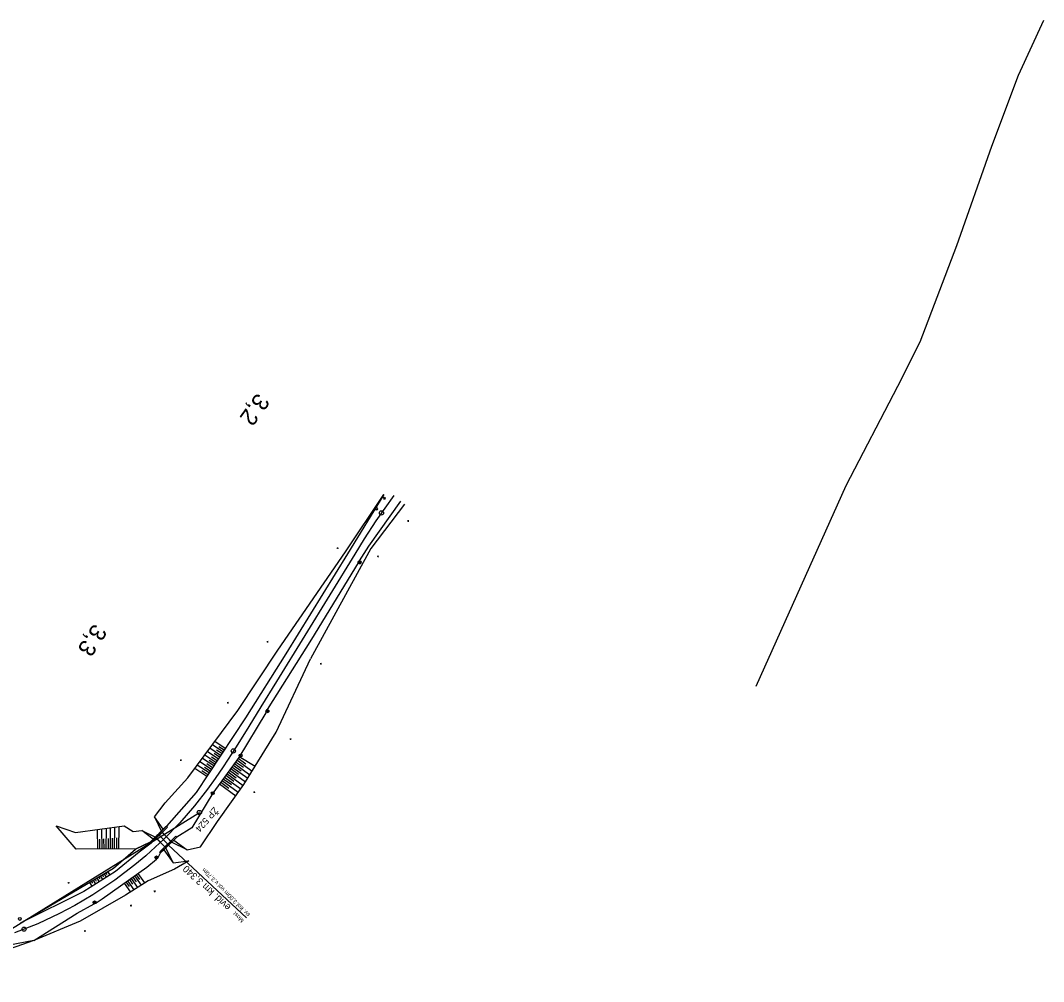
# Model space of a CAD drawing. Extents: x -738085 to -734426, y -1122197 to -1119748.
# Drawn here: x -736607.8 to -736243, y -1121765.3 to -1121422.7 of the extents above; entities that cross this region are included whole.
import ezdxf

# ---------------------------------------------------------------- set-up
doc = ezdxf.new("R2010")
doc.units = 0
for name, color, linetype in [('Polygon ku', 7, 'Continuous'), ('Vrstva 1', 7, 'Continuous'), ('Vrstva 11', 7, 'Continuous'), ('Vrstva 12', 7, 'Continuous'), ('Vrstva 17', 7, 'Continuous'), ('Vrstva 18', 7, 'Continuous'), ('Vrstva 4', 7, 'Continuous'), ('Vrstva 48', 7, 'Continuous'), ('Vrstva 49', 7, 'Continuous'), ('Vrstva 63', 7, 'Continuous'), ('Vrstva 7', 7, 'Continuous')]:
    doc.layers.add(name, color=color, linetype=linetype)

msp = doc.modelspace()

# ---------------------------------------------------------------- linework, layer by layer
at = {"layer": 'Polygon ku'}
for points in [[(-736242.99, -1121422.7), (-736252.08, -1121442.26), (-736261.55, -1121467.67), (-736274.03, -1121502.97), (-736287.1, -1121537.41), (-736295.04, -1121553.12)], [(-736295.04, -1121553.12), (-736313.43, -1121588.53), (-736345.56, -1121660.08)]]:
    msp.add_lwpolyline(points, dxfattribs=at)
at = {"layer": 'Vrstva 1'}
msp.add_lwpolyline([(-736474.59, -1121592.04), (-736481.1, -1121601.1), (-736485.16, -1121607.48), (-736488.53, -1121612.91), (-736506.33, -1121641.86), (-736516.48, -1121658.33), (-736522.03, -1121667.33), (-736526.39, -1121674.4), (-736530.86, -1121681.54), (-736535.51, -1121688.71), (-736538.31, -1121692.85), (-736541.08, -1121696.68), (-736545.71, -1121702.61), (-736550.96, -1121708.65), (-736556.62, -1121714.46), (-736561.26, -1121718.81), (-736563.11, -1121720.47), (-736566.92, -1121723.66), (-736574.05, -1121729.09), (-736581.91, -1121734.35), (-736588.31, -1121738.11), (-736593.86, -1121741.02), (-736601.6, -1121744.63), (-736609.85, -1121747.92)], dxfattribs=at)
msp.add_lwpolyline([(-736474.59, -1121592.04), (-736481.1, -1121601.1), (-736485.16, -1121607.48), (-736488.53, -1121612.91), (-736506.33, -1121641.86), (-736516.48, -1121658.33), (-736522.03, -1121667.33), (-736526.39, -1121674.4), (-736530.86, -1121681.54), (-736535.51, -1121688.71), (-736538.31, -1121692.85), (-736541.08, -1121696.68), (-736545.71, -1121702.61), (-736550.96, -1121708.65), (-736556.62, -1121714.46), (-736561.26, -1121718.81), (-736563.11, -1121720.47), (-736566.92, -1121723.66), (-736574.05, -1121729.09), (-736581.91, -1121734.35), (-736588.31, -1121738.11), (-736593.86, -1121741.02), (-736601.6, -1121744.63), (-736609.85, -1121747.92)], dxfattribs=at)
at = {"layer": 'Vrstva 11'}
for p, q in [((-736487.1, -1121615.42), (-736486.89, -1121616.32)), ((-736486.73, -1121615.34), (-736486.52, -1121616.23)), ((-736519.97, -1121668.45), (-736519.75, -1121669.35)), ((-736519.6, -1121668.37), (-736519.39, -1121669.25)), ((-736539.47, -1121697.71), (-736539.32, -1121698.62)), ((-736539.1, -1121697.65), (-736538.95, -1121698.56)), ((-736559.44, -1121720.55), (-736559.47, -1121721.47)), ((-736559.07, -1121720.56), (-736559.1, -1121721.48)), ((-736581.37, -1121736.54), (-736581.61, -1121737.44)), ((-736581.01, -1121736.64), (-736581.24, -1121737.52))]:
    msp.add_line(p, q, dxfattribs=at)
for centre in [(-736486.82, -1121615.83), (-736519.69, -1121668.85), (-736539.22, -1121698.14), (-736559.28, -1121721.01), (-736581.32, -1121737.03)]:
    msp.add_circle(centre, 0.5, dxfattribs=at)
at = {"layer": 'Vrstva 12'}
for p, q in [((-736486.31, -1121615.66), (-736486.69, -1121616.38)), ((-736519.14, -1121668.73), (-736519.56, -1121669.41)), ((-736558.71, -1121721.04), (-736559.31, -1121721.58)), ((-736580.75, -1121737.18), (-736581.46, -1121737.6))]:
    msp.add_line(p, q, dxfattribs=at)
for points in [[(-736487.37, -1121615.96), (-736486.95, -1121615.28), (-736486.31, -1121615.66), (-736486.69, -1121616.38), (-736487.37, -1121615.96)], [(-736486.95, -1121615.28), (-736486.31, -1121615.66), (-736486.31, -1121615.66)], [(-736487.37, -1121615.96), (-736486.69, -1121616.38), (-736486.69, -1121616.38)], [(-736520.24, -1121668.99), (-736519.82, -1121668.3), (-736519.14, -1121668.73), (-736519.56, -1121669.41), (-736520.24, -1121668.99)], [(-736520.24, -1121668.99), (-736519.56, -1121669.41), (-736519.56, -1121669.41)], [(-736519.82, -1121668.3), (-736519.14, -1121668.73), (-736519.14, -1121668.73)], [(-736559.84, -1121720.98), (-736559.25, -1121720.45), (-736558.71, -1121721.04), (-736559.31, -1121721.58), (-736559.84, -1121720.98)], [(-736559.84, -1121720.98), (-736559.31, -1121721.58), (-736559.31, -1121721.58)], [(-736559.25, -1121720.45), (-736558.71, -1121721.04), (-736558.71, -1121721.04)], [(-736581.88, -1121736.89), (-736581.17, -1121736.46), (-736580.75, -1121737.18), (-736581.46, -1121737.6), (-736581.88, -1121736.89)], [(-736581.88, -1121736.89), (-736581.46, -1121737.6), (-736581.46, -1121737.6)], [(-736581.17, -1121736.46), (-736580.75, -1121737.18), (-736580.75, -1121737.18)]]:
    msp.add_lwpolyline(points, dxfattribs=at)
at = {"layer": 'Vrstva 17'}
for p, q in [((-736555.89, -1121710.05), (-736561.02, -1121715.26)), ((-736557.56, -1121719.19), (-736552.26, -1121714.01))]:
    msp.add_line(p, q, dxfattribs=at)
at = {"layer": 'Vrstva 18'}
for p, q in [((-736561.46, -1121715.57), (-736555.68, -1121709.93)), ((-736555.68, -1121709.93), (-736555.68, -1121709.93)), ((-736559.61, -1121713.85), (-736559.61, -1121713.9)), ((-736559.61, -1121713.85), (-736555.92, -1121717.57)), ((-736559.61, -1121713.9), (-736556.03, -1121717.53)), ((-736558.51, -1121712.82), (-736554.94, -1121716.5)), ((-736557.47, -1121711.79), (-736556.94, -1121712.33)), ((-736557.47, -1121711.79), (-736553.86, -1121715.52)), ((-736556.94, -1121712.33), (-736553.86, -1121715.45)), ((-736552.06, -1121713.78), (-736552.38, -1121713.44)), ((-736552.06, -1121713.78), (-736552.06, -1121713.78)), ((-736555.92, -1121717.57), (-736556.03, -1121717.53)), ((-736554.98, -1121716.66), (-736527.18, -1121742.52)), ((-736553.86, -1121715.52), (-736553.86, -1121715.45)), ((-736558.11, -1121719.07), (-736558.11, -1121719.07)), ((-736558.11, -1121719.07), (-736557.78, -1121719.42)), ((-736557.78, -1121719.42), (-736557.78, -1121719.42))]:
    msp.add_line(p, q, dxfattribs=at)
for points in [[(-736555.68, -1121709.93), (-736556.82, -1121710.98), (-736559.91, -1121706.53), (-736557.47, -1121711.79), (-736556.82, -1121710.98)], [(-736561.46, -1121715.57), (-736561.14, -1121715.9), (-736555.38, -1121710.29), (-736555.68, -1121709.93), (-736561.46, -1121715.57)], [(-736555.38, -1121710.29), (-736561.14, -1121715.9), (-736561.46, -1121715.57), (-736561.46, -1121715.57)], [(-736555.38, -1121710.29), (-736555.38, -1121710.29), (-736555.68, -1121709.93)], [(-736561.46, -1121715.57), (-736560.43, -1121714.5), (-736564.53, -1121711.39), (-736559.61, -1121713.85), (-736560.43, -1121714.5)], [(-736552.38, -1121713.44), (-736552.38, -1121713.44), (-736558.11, -1121719.07)], [(-736552.38, -1121713.44), (-736552.06, -1121713.78), (-736557.78, -1121719.42), (-736558.11, -1121719.07), (-736552.38, -1121713.44)], [(-736552.38, -1121713.44), (-736552.06, -1121713.78), (-736557.78, -1121719.42), (-736558.11, -1121719.07), (-736552.38, -1121713.44)], [(-736552.06, -1121713.78), (-736553.05, -1121714.83), (-736548.27, -1121718.36), (-736553.86, -1121715.52)], [(-736557.78, -1121719.42), (-736556.6, -1121718.34), (-736553.28, -1121722.94), (-736555.92, -1121717.57), (-736556.6, -1121718.34)]]:
    msp.add_lwpolyline(points, dxfattribs=at)
for centre, major_axis, ratio, start_param, end_param in [((-736558.28, -1121713.11), (1.34, 0.78), 0.230715, 6.243976, 9.45735), ((-736554.95, -1121716.49), (-1.09, -1.04), 0.009083, 0.017637, 3.105351)]:
    msp.add_ellipse(centre, major_axis=major_axis, ratio=ratio, start_param=start_param, end_param=end_param, dxfattribs=at)
at = {"layer": 'Vrstva 4'}
msp.add_line((-736555.38, -1121710.29), (-736561.14, -1121715.9), dxfattribs=at)
at = {"layer": 'Vrstva 48'}
for p, q in [((-736535.56, -1121683.4), (-736539.31, -1121680.93)), ((-736534.74, -1121682.14), (-736538.42, -1121679.72)), ((-736538.04, -1121687.16), (-736542, -1121684.54)), ((-736537.21, -1121685.9), (-736541.11, -1121683.34)), ((-736536.39, -1121684.65), (-736540.21, -1121682.13)), ((-736536.8, -1121685.28), (-736538.73, -1121684.01)), ((-736535.97, -1121684.02), (-736537.87, -1121682.78)), ((-736535.15, -1121682.77), (-736537.01, -1121681.55)), ((-736529.73, -1121685.06), (-736524.06, -1121688.5)), ((-736540.51, -1121690.91), (-736544.7, -1121688.16)), ((-736539.69, -1121689.66), (-736543.8, -1121686.95)), ((-736538.86, -1121688.41), (-736542.9, -1121685.75)), ((-736539.27, -1121689.03), (-736541.31, -1121687.69)), ((-736538.45, -1121687.78), (-736540.45, -1121686.46)), ((-736537.62, -1121686.53), (-736539.59, -1121685.23)), ((-736532.35, -1121688.71), (-736526.73, -1121692.81)), ((-736531.91, -1121688.11), (-736529.12, -1121690.14)), ((-736531.47, -1121687.5), (-736525.94, -1121691.53)), ((-736531.03, -1121686.9), (-736528.28, -1121688.9)), ((-736530.58, -1121686.29), (-736525.15, -1121690.26)), ((-736530.14, -1121685.68), (-736527.45, -1121687.65)), ((-736541.34, -1121692.17), (-736545.59, -1121689.36)), ((-736540.92, -1121691.54), (-736543.03, -1121690.15)), ((-736540.1, -1121690.29), (-736542.17, -1121688.92)), ((-736535, -1121692.35), (-736529.2, -1121696.58)), ((-736534.56, -1121691.74), (-736531.67, -1121693.85)), ((-736534.12, -1121691.14), (-736528.33, -1121695.35)), ((-736533.68, -1121690.53), (-736530.8, -1121692.63)), ((-736533.24, -1121689.93), (-736527.52, -1121694.09)), ((-736532.79, -1121689.32), (-736529.96, -1121691.39)), ((-736536.77, -1121694.78), (-736530.95, -1121699.02)), ((-736536.33, -1121694.17), (-736533.42, -1121696.29)), ((-736535.89, -1121693.56), (-736530.08, -1121697.8)), ((-736535.45, -1121692.96), (-736532.54, -1121695.07)), ((-736577.17, -1121717.96), (-736577.11, -1121710.6)), ((-736575.67, -1121717.97), (-736575.61, -1121710.4)), ((-736574.17, -1121717.98), (-736574.11, -1121710.19)), ((-736572.67, -1121717.99), (-736572.61, -1121709.98)), ((-736580.17, -1121717.99), (-736580.28, -1121711.04)), ((-736578.67, -1121717.96), (-736578.78, -1121710.83)), ((-736576.42, -1121717.96), (-736576.39, -1121714.23)), ((-736574.92, -1121717.97), (-736574.89, -1121714.13)), ((-736573.42, -1121717.99), (-736573.39, -1121714.03)), ((-736579.42, -1121717.98), (-736579.47, -1121714.46)), ((-736577.92, -1121717.95), (-736577.98, -1121714.34)), ((-736581.16, -1121728.78), (-736580.76, -1121729.44)), ((-736580.51, -1121728.4), (-736579.74, -1121729.7)), ((-736579.86, -1121728.02), (-736579.48, -1121728.66)), ((-736579.22, -1121727.64), (-736578.47, -1121728.9)), ((-736578.57, -1121727.26), (-736578.2, -1121727.88)), ((-736577.93, -1121726.87), (-736577.2, -1121728.1)), ((-736577.28, -1121726.49), (-736576.93, -1121727.09)), ((-736576.64, -1121726.11), (-736575.94, -1121727.29)), ((-736568.31, -1121728.48), (-736566.02, -1121731.73)), ((-736567.7, -1121728.05), (-736566.54, -1121729.69)), ((-736567.08, -1121727.62), (-736564.76, -1121730.92)), ((-736566.47, -1121727.18), (-736565.3, -1121728.85)), ((-736565.86, -1121726.75), (-736563.49, -1121730.11)), ((-736583.09, -1121729.93), (-736582.28, -1121731.31)), ((-736582.45, -1121729.55), (-736582.04, -1121730.23)), ((-736581.8, -1121729.17), (-736581.01, -1121730.51)), ((-736570.76, -1121730.21), (-736568.56, -1121733.34)), ((-736570.15, -1121729.77), (-736569.04, -1121731.36)), ((-736569.54, -1121729.34), (-736567.29, -1121732.53)), ((-736568.92, -1121728.91), (-736567.79, -1121730.52))]:
    msp.add_line(p, q, dxfattribs=at)
at = {"layer": 'Vrstva 49'}
for p, q in [((-736469.3, -1121601.06), (-736469.8, -1121601.15)), ((-736469.59, -1121600.86), (-736469.51, -1121601.35)), ((-736494.44, -1121610.75), (-736494.93, -1121610.87)), ((-736494.74, -1121610.57), (-736494.62, -1121611.05)), ((-736480.06, -1121613.66), (-736480.54, -1121613.77)), ((-736480.36, -1121613.47), (-736480.24, -1121613.96)), ((-736519.45, -1121644.09), (-736519.94, -1121644.2)), ((-736519.75, -1121643.9), (-736519.64, -1121644.39)), ((-736500.47, -1121651.91), (-736500.95, -1121652.03)), ((-736500.77, -1121651.73), (-736500.65, -1121652.21)), ((-736533.62, -1121665.82), (-736534.1, -1121665.94)), ((-736533.92, -1121665.64), (-736533.8, -1121666.13)), ((-736511.28, -1121678.79), (-736511.77, -1121678.91)), ((-736511.58, -1121678.61), (-736511.47, -1121679.09)), ((-736550.31, -1121686.35), (-736550.8, -1121686.43)), ((-736550.6, -1121686.15), (-736550.52, -1121686.64)), ((-736524.17, -1121697.74), (-736524.66, -1121697.84)), ((-736524.46, -1121697.55), (-736524.37, -1121698.04)), ((-736590.35, -1121730.16), (-736590.83, -1121730.04)), ((-736590.53, -1121729.86), (-736590.65, -1121730.34)), ((-736559.66, -1121733.13), (-736560.16, -1121733.06)), ((-736559.88, -1121732.85), (-736559.94, -1121733.34)), ((-736568.11, -1121738.25), (-736568.6, -1121738.16)), ((-736568.3, -1121737.96), (-736568.4, -1121738.45)), ((-736584.7, -1121747.01), (-736584.85, -1121747.49)), ((-736584.54, -1121747.32), (-736585.02, -1121747.18))]:
    msp.add_line(p, q, dxfattribs=at)
for points in [[(-736559.91, -1121706.53), (-736556.14, -1121701.52), (-736548.08, -1121692.7), (-736530.2, -1121668.69), (-736516, -1121647.1), (-736491.86, -1121612.07), (-736478.23, -1121591.65)], [(-736478.23, -1121591.65), (-736491.19, -1121612.76), (-736513.16, -1121648.49), (-736527.57, -1121671.26), (-736545.1, -1121697.88), (-736555.68, -1121709.93), (-736556.82, -1121710.98), (-736559.91, -1121706.53)], [(-736470.88, -1121595.11), (-736482.84, -1121610.96), (-736504.31, -1121650.26)], [(-736472.2, -1121594.02), (-736483.63, -1121610.05), (-736486.95, -1121615.28), (-736487.37, -1121615.96), (-736503.97, -1121643.18)], [(-736503.97, -1121643.18), (-736519.82, -1121668.3), (-736520.24, -1121668.99), (-736520.25, -1121669.42), (-736529.95, -1121685.41), (-736539.22, -1121698.14), (-736546.66, -1121710.46), (-736552.06, -1121713.78), (-736553.05, -1121714.83), (-736548.27, -1121718.36)], [(-736548.27, -1121718.36), (-736543.58, -1121717.29), (-736537.46, -1121708.17), (-736528.08, -1121694.99), (-736516.53, -1121676.34), (-736504.31, -1121650.26)], [(-736594.99, -1121709.79), (-736588.15, -1121712.12), (-736570.82, -1121709.74), (-736567.62, -1121711.77), (-736564.53, -1121711.39)], [(-736561.46, -1121715.57), (-736566.72, -1121718.04), (-736577.85, -1121717.95), (-736587.95, -1121718.11), (-736594.99, -1121709.79)], [(-736561.46, -1121715.57), (-736560.43, -1121714.5), (-736564.53, -1121711.39)], [(-736607.6, -1121744.3), (-736586.81, -1121732.14), (-736574.59, -1121724.9), (-736566.72, -1121718.04), (-736561.46, -1121715.57), (-736561.14, -1121715.9)], [(-736561.14, -1121715.9), (-736565.4, -1121719.15), (-736573.9, -1121726.01)], [(-736602.93, -1121750.62), (-736587.49, -1121740.86), (-736581.46, -1121737.6), (-736580.75, -1121737.18), (-736578.66, -1121735.76), (-736562.65, -1121724.5), (-736559.31, -1121721.58), (-736558.71, -1121721.04), (-736557.78, -1121719.42), (-736556.6, -1121718.34), (-736553.28, -1121722.94)], [(-736553.28, -1121722.94), (-736547.76, -1121722.28), (-736552.84, -1121725.23), (-736562.24, -1121729.32), (-736570.28, -1121734.44), (-736586.44, -1121743.69), (-736602.93, -1121750.62)], [(-736602.93, -1121750.62), (-736618.59, -1121753.56), (-736637.64, -1121757.68), (-736638.02, -1121757.55), (-736638.82, -1121757.65), (-736659.7, -1121759.54), (-736670.41, -1121758.99), (-736671.41, -1121758.94), (-736678.34, -1121758.86), (-736698.35, -1121754.91), (-736698.8, -1121754.73), (-736699.57, -1121754.51), (-736713.56, -1121750.47), (-736743.53, -1121735.92), (-736755.42, -1121728.39)], [(-736573.9, -1121726.01), (-736585.2, -1121733.16), (-736607.6, -1121744.3)], [(-736602.93, -1121750.62), (-736617.95, -1121755.82), (-736639.5, -1121761.37), (-736654.03, -1121764.61), (-736658.53, -1121764.79), (-736677.92, -1121765.25), (-736698.72, -1121762.11), (-736730.37, -1121750.67), (-736758.07, -1121729.16)]]:
    msp.add_lwpolyline(points, dxfattribs=at)
at = {"layer": 'Vrstva 63'}
for p, q in [((-736634.91, -1121761.31), (-736543.96, -1121705)), ((-736543.93, -1121704.96), (-736543.99, -1121705.03))]:
    msp.add_line(p, q, dxfattribs=at)
msp.add_circle((-736543.96, -1121705), 0.756, dxfattribs=at)
at = {"layer": 'Vrstva 7'}
for p, q in [((-736477.64, -1121593.29), (-736478.45, -1121592.71)), ((-736477.76, -1121592.59), (-736478.34, -1121593.41)), ((-736480.98, -1121596.76), (-736481.04, -1121596.84)), ((-736529.22, -1121684.68), (-736529.27, -1121684.77))]:
    msp.add_line(p, q, dxfattribs=at)
for centre, radius in [((-736481.01, -1121596.8), 0.5), ((-736479.04, -1121598.23), 0.75), ((-736479.04, -1121598.23), 0.75), ((-736531.84, -1121683.05), 0.75), ((-736531.84, -1121683.05), 0.75), ((-736529.25, -1121684.73), 0.5), ((-736607.96, -1121742.95), 0.5), ((-736606.51, -1121746.59), 0.75), ((-736606.51, -1121746.59), 0.75)]:
    msp.add_circle(centre, radius, dxfattribs=at)

# ---------------------------------------------------------------- texts
at = {"layer": 'Vrstva 18'}
for s, height, rotation, p in [('evid. km 3,340', 2.5, 137.0555, (-736532.56, -1121738.45)), ('sv. kol.3,00m vol.v.3,70m', 1.5, 134.4601, (-736525.77, -1121741.31)), ('Most', 1.5, 134.4601, (-736527.91, -1121743.41))]:
    msp.add_text(s, height=height, rotation=rotation, dxfattribs=at).set_placement(p)
at = {"layer": 'Vrstva 63'}
msp.add_text('ŽP 524', height=2.4, rotation=228.9893, dxfattribs=at).set_placement((-736538.8, -1121702.84))
at = {"layer": 'Vrstva 7'}
for s, rotation, p in [('3,2', 234.2755, (-736523.35, -1121555.17)), ('3,2', 234.2755, (-736523.35, -1121555.17)), ('3,3', 237.0514, (-736581.55, -1121637.37)), ('3,3', 237.0514, (-736581.55, -1121637.37))]:
    msp.add_text(s, height=6, rotation=rotation, dxfattribs=at).set_placement(p)

doc.saveas('drawing.dxf')
